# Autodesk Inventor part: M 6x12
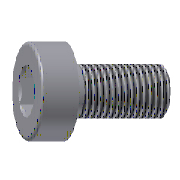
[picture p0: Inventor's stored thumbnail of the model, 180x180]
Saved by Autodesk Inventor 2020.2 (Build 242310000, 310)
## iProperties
Manager: www.cadconsulting.pl
Company: Fabian Stasiak CAD Consulting
Created: 2014-02
Part Number: M 6x12
Material: Stal, miękka
Description: Socket Head Cap Screw DIN 912 - 12.9
Document SubType Name: Modeling
Designer: F.Stasiak
Standard Revision: 1
Manufacturer: DME
Language: pl-PL
Size Designation: 6x12
Categories: <MemberInstance><Categories><Category DisplayName="Forma wtryskowa" InternalName="349578f2-f4d4-4954-8c09-8e99297a61c0" Mnemonic="MOLD"><Category DisplayName="C
Mass: 0.133121 g
Surface Area: 2.01441 cm^2
Volume: 0.133121 cm^3
Density: 7.85 g/cm^3
Appearance: Częściowo polerowana
Catalog Web Link: www.expertbooks.pl
IsCustomPart: 0
Author: F.Stasiak
Subject: Zbiór ćwiczeń. Autodesk Inventor 2020. Kurs Professional
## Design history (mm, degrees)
sketch "Sketch1"
  geometry: L1 (0, -15.6)-(0, 9.6) reference; L2 (2.887, 6)-(5, 6); L3 (5, 6)-(5, 0); L4 (5, 0)-(3, 0); L5 (3, 0)-(3, -12); L6 (3, -12)-(0, -12); L7 (0, 1.498)-(0, -12); L8 (0, 1.498)-(2.5, 3); L9 (2.5, 3)-(2.5, 5.613); L10 (2.5, 5.613)-(2.887, 6); 1 further point
  constraints: 18 end point, 4 vertical, 3 horizontal, 2 point on line
  dimensions: "d0" = 10 diameter of L3 L1 (= dk); "d1" = 6 distance between parallel lines of L4 L2 (= k); "d2" = 6 diameter of L5 L1 (= d); "d3" = 12 distance between parallel lines of L6 L4 (= L); "d4" = 59 deg angle of L1 L8; "d5" = 45 deg angle of L1 L10; "d6" = 5 diameter of L9 L1 (= sw); "d7" = 5.7735 diameter of L2.start L1 (= 1.1547 x sw); "d8" = 3 distance from line of L8.end L2 (= t)
revolve "Revolution1" sketch "Sketch1" stored, may be unused: angle "d44" = 90 deg
sketch "Sketch2"
  geometry: L1 (0, 2.887)-(2.5, 1.443); L2 (2.5, 1.443)-(2.5, -1.443); L3 (2.5, -1.443)-(0, -2.887); L4 (0, -2.887)-(-2.5, -1.443); L5 (-2.5, -1.443)-(-2.5, 1.443); L6 (-2.5, 1.443)-(0, 2.887); 3 further points
  constraints: 12 end point, 2 vertical alignment, 1 coincident, 14 other
extrude "Extrusion1" cut sketch "Sketch2" taper "d9" = 0 deg; stored distance "d45" = 10
thread "Thread1" dims "d10" = 12 (= b), "d11" = 0
chamfer "Chamfer1" distance "d12" = 0.5 (= 0.5 x P); stored, may be unused: second distance "d50" = 2, angle "d51" = 45 deg
fillet "Fillet1" dims "d13" = 0.5 (= 0.5 x P)
body "Solid1"
other parameters: "d" = 6 [user parameter; used in 1 equation term], "L" = 12 [user parameter; used in 1 equation term], "dk" = 10 [user parameter; used in 1 equation term], "b" = 12 [user parameter; used in 1 equation term], "k" = 6 [user parameter; used in 1 equation term], "sw" = 5 [user parameter; used in 2 equation terms], "t" = 3 [user parameter; used in 1 equation term], "P" = 1 [user parameter; used in 2 equation terms], "d14" = 0, "d15" = 0, "d55" = 0
